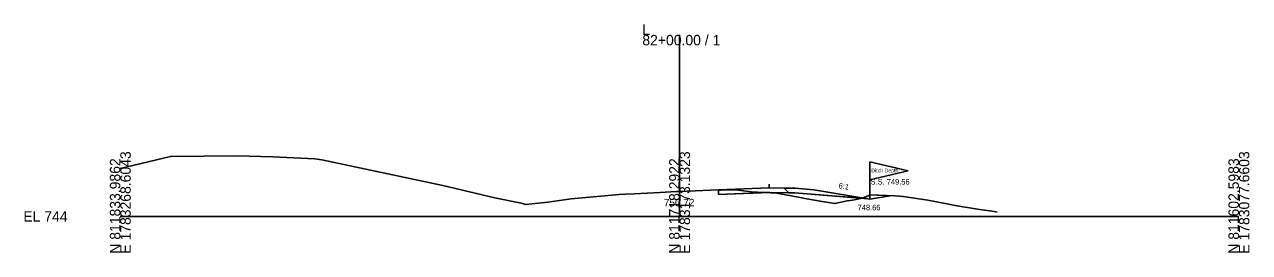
# Model space of a CAD drawing. Extents: x -26 to 7903, y -10 to 9573.
# Drawn here: x 4974.3 to 5302.8, y 2990.3 to 3051.5 of the extents above; entities that cross this region are included whole.
import ezdxf

# ---------------------------------------------------------------- set-up
doc = ezdxf.new("R2010")
doc.units = 0
for name, color, linetype in [('Exist Cross Section Cell', 7, 'Continuous'), ('Exist XS Center Line Elevation Label', 7, 'Continuous'), ('Exist XS Ground Line', 7, 'Continuous'), ('Prop XS Ditch Slope Text', 7, 'Continuous'), ('Prop XS Ditch Standard Text', 7, 'Continuous'), ('Prop XS Dump Level', 7, 'Continuous'), ('Prop XS Earthwork Shape', 7, 'Continuous'), ('Prop XS EOT Tick Mark', 7, 'Continuous'), ('Prop XS Finish Grade', 7, 'Continuous'), ('Prop XS Finish Grade Earthwork', 7, 'Continuous'), ('Prop XS Finish Grade Paved Shoulder', 7, 'Continuous'), ('Prop XS Finish Grade Pavement', 7, 'Continuous'), ('Prop XS Pvmt Edge Slope', 7, 'Continuous'), ('Prop XS SS Elevation Text', 7, 'Continuous'), ('Prop XS Subgrade Earthwork', 7, 'Continuous'), ('Scratch_Level_3', 7, 'Continuous'), ('Scratch_Level_6', 7, 'Continuous')]:
    doc.layers.add(name, color=color, linetype=linetype)

msp = doc.modelspace()

# ---------------------------------------------------------------- linework, layer by layer
at = {"layer": 'Exist Cross Section Cell'}
for p, q in [((5150, 3000), (5150, 3048.74)), ((5000, 3000), (5150, 3000)), ((5150, 3000), (5300, 3000))]:
    msp.add_line(p, q, dxfattribs=at)
at = {"layer": 'Exist XS Ground Line'}
for p, q in [((5000, 3012.87), (5013.42, 3016.09)), ((5013.42, 3016.09), (5031.35, 3016.25)), ((5031.35, 3016.25), (5040.91, 3016)), ((5040.91, 3016), (5052.18, 3015.49)), ((5052.18, 3015.49), (5054.09, 3015.2)), ((5054.09, 3015.2), (5086.47, 3008.3)), ((5086.47, 3008.3), (5100.41, 3005.03)), ((5135.44, 3005.96), (5137.8, 3006.09)), ((5137.8, 3006.09), (5144.78, 3006.46)), ((5144.78, 3006.46), (5149.11, 3006.69)), ((5149.11, 3006.69), (5150, 3006.72)), ((5150, 3006.72), (5160.46, 3007.15)), ((5160.46, 3007.15), (5165.08, 3007.1)), ((5165.08, 3007.1), (5169.87, 3006.55)), ((5169.87, 3006.55), (5170.25, 3006.5)), ((5170.25, 3006.5), (5170.86, 3006.5)), ((5170.86, 3006.5), (5176.09, 3006.28)), ((5176.09, 3006.28), (5182.29, 3005.09)), ((5100.41, 3005.03), (5107.5, 3003.53)), ((5107.5, 3003.53), (5108.8, 3003.24)), ((5108.8, 3003.24), (5110.47, 3003.39)), ((5110.47, 3003.39), (5114.69, 3003.85)), ((5114.69, 3003.85), (5120.27, 3004.62)), ((5120.27, 3004.62), (5120.89, 3004.68)), ((5120.89, 3004.68), (5132.8, 3005.77)), ((5132.8, 3005.77), (5133.76, 3005.86)), ((5133.76, 3005.86), (5135.44, 3005.96)), ((5182.29, 3005.09), (5183.19, 3004.92)), ((5183.19, 3004.92), (5183.58, 3004.85)), ((5183.58, 3004.85), (5186.73, 3004.28)), ((5186.73, 3004.28), (5188.19, 3004.03)), ((5188.19, 3004.03), (5188.85, 3003.9)), ((5188.85, 3003.9), (5191.67, 3003.47)), ((5191.67, 3003.47), (5194.98, 3004.16)), ((5194.98, 3004.16), (5196.34, 3004.39)), ((5196.34, 3004.39), (5199.03, 3004.93)), ((5199.03, 3004.93), (5201.17, 3005.8)), ((5201.17, 3005.8), (5207.75, 3005.5)), ((5207.75, 3005.5), (5208.95, 3005.47)), ((5208.95, 3005.47), (5209.98, 3005.34)), ((5209.98, 3005.34), (5216.56, 3004.41)), ((5216.56, 3004.41), (5221.19, 3003.47)), ((5221.19, 3003.47), (5223.92, 3002.95)), ((5223.92, 3002.95), (5229.89, 3001.95)), ((5229.89, 3001.95), (5234.38, 3001.29)), ((5234.38, 3001.29), (5234.71, 3001.24)), ((5234.71, 3001.24), (5235.21, 3001.16))]:
    msp.add_line(p, q, dxfattribs=at)
at = {"layer": 'Prop XS Dump Level'}
for p, q in [((5201, 3009.86), (5201, 3014.66)), ((5201, 3014.66), (5211.3, 3012.26)), ((5211.3, 3012.26), (5201, 3009.86)), ((5201, 3004.66), (5201, 3009.86)), ((5160.43, 3007.14), (5174, 3007.68))]:
    msp.add_line(p, q, dxfattribs=at)
at = {"layer": 'Prop XS Earthwork Shape'}
for points in [[(5169.87, 3006.55), (5170.25, 3006.5), (5170.86, 3006.5), (5173.17, 3006.4), (5160.46, 3005.89), (5160.46, 3007.15), (5165.08, 3007.1)], [(5188.19, 3004.03), (5188.85, 3003.9), (5191.67, 3003.47), (5194.98, 3004.16), (5196.34, 3004.39), (5198.77, 3004.88), (5180.94, 3006.31), (5179.28, 3006.34), (5174.19, 3006.44), (5173.17, 3006.4), (5176.09, 3006.28), (5182.29, 3005.09), (5183.19, 3004.92), (5183.58, 3004.85), (5186.73, 3004.28)], [(5200.47, 3004.75), (5201, 3004.66), (5206.43, 3005.56), (5201.17, 3005.8), (5199.03, 3004.93), (5198.77, 3004.88)]]:
    msp.add_lwpolyline(points, close=True, dxfattribs=at)
at = {"layer": 'Prop XS EOT Tick Mark'}
msp.add_line((5174, 3007.7), (5174, 3008.7), dxfattribs=at)
at = {"layer": 'Prop XS Finish Grade'}
for p, q in [((5178, 3007.62), (5181, 3007.56)), ((5181, 3007.56), (5186, 3007.16)), ((5186, 3007.16), (5200.47, 3004.75))]:
    msp.add_line(p, q, dxfattribs=at)
at = {"layer": 'Prop XS Finish Grade Earthwork'}
for p, q in [((5200.47, 3004.75), (5201, 3004.66)), ((5201, 3004.66), (5206.43, 3005.56))]:
    msp.add_line(p, q, dxfattribs=at)
at = {"layer": 'Prop XS Finish Grade Paved Shoulder'}
msp.add_line((5174, 3007.7), (5178, 3007.62), dxfattribs=at)
at = {"layer": 'Prop XS Finish Grade Pavement'}
msp.add_line((5160.46, 3007.15), (5174, 3007.7), dxfattribs=at)
at = {"layer": 'Prop XS Pvmt Edge Slope'}
msp.add_line((5178, 3007.62), (5179.28, 3006.34), dxfattribs=at)
at = {"layer": 'Prop XS Subgrade Earthwork'}
for p, q in [((5160.46, 3005.89), (5160.46, 3007.15)), ((5160.46, 3005.89), (5174.19, 3006.44)), ((5174.19, 3006.44), (5179.28, 3006.34)), ((5179.28, 3006.34), (5180.94, 3006.31)), ((5180.94, 3006.31), (5200.47, 3004.75))]:
    msp.add_line(p, q, dxfattribs=at)
at = {"layer": 'Scratch_Level_3'}
for p, q in [((5181, 3007.56), (5178, 3007.62)), ((5178, 3007.62), (5179.28, 3006.34)), ((5179.28, 3006.34), (5180.94, 3006.31)), ((5180.94, 3006.31), (5200.47, 3004.75)), ((5186, 3007.16), (5181, 3007.56)), ((5200.47, 3004.75), (5186, 3007.16))]:
    msp.add_line(p, q, dxfattribs=at)
at = {"layer": 'Scratch_Level_6'}
for points in [[(5170.86, 3006.5), (5173.17, 3006.4), (5160.46, 3005.89), (5160.46, 3007.15), (5165.08, 3007.1), (5169.87, 3006.55), (5170.25, 3006.5)], [(5199.03, 3004.93), (5199.12, 3004.97), (5200.47, 3004.75), (5198.77, 3004.88)]]:
    msp.add_lwpolyline(points, close=True, dxfattribs=at)

# ---------------------------------------------------------------- texts
at = {"layer": 'Exist Cross Section Cell'}
for s, p in [('82+00.00 / 1', (5140, 3045.94)), ('L', (5140, 3048.74)), ('EL 744', (4974, 2998.6))]:
    msp.add_text(s, height=2.8, dxfattribs=at).set_placement(p)
for s, p in [('E 1783268.6043', (5002.8, 2990)), ('E 1783173.1323', (5152.8, 2990)), ('E 1783077.6603', (5302.8, 2990)), ('N 811833.9862', (5000, 2990)), ('N 811718.2922', (5150, 2990)), ('N 811602.5983', (5300, 2990))]:
    msp.add_text(s, height=2.8, rotation=90, dxfattribs=at).set_placement(p)
at = {"layer": 'Exist XS Center Line Elevation Label'}
msp.add_text('750.72', height=2, dxfattribs=at).set_placement((5145.79, 3002.72))
at = {"layer": 'Prop XS Ditch Slope Text'}
msp.add_text('6:1', height=1.5, rotation=350.5377, dxfattribs=at).set_placement((5192.55, 3007.59))
at = {"layer": 'Prop XS Ditch Standard Text'}
msp.add_text('748.66', height=1.5, dxfattribs=at).set_placement((5197.74, 3001.66))
at = {"layer": 'Prop XS Dump Level'}
for s, height, p in [('Ditch Depth', 1, (5201.44, 3011.83)), ('Eop', 0.3, (5160.46, 3006.85)), ('Case4', 0.04, (5186, 3007.12))]:
    msp.add_text(s, height=height, dxfattribs=at).set_placement(p)
at = {"layer": 'Prop XS SS Elevation Text'}
msp.add_text('S.S. 749.56', height=1.5, dxfattribs=at).set_placement((5201.21, 3008.56))

doc.saveas('drawing.dxf')
